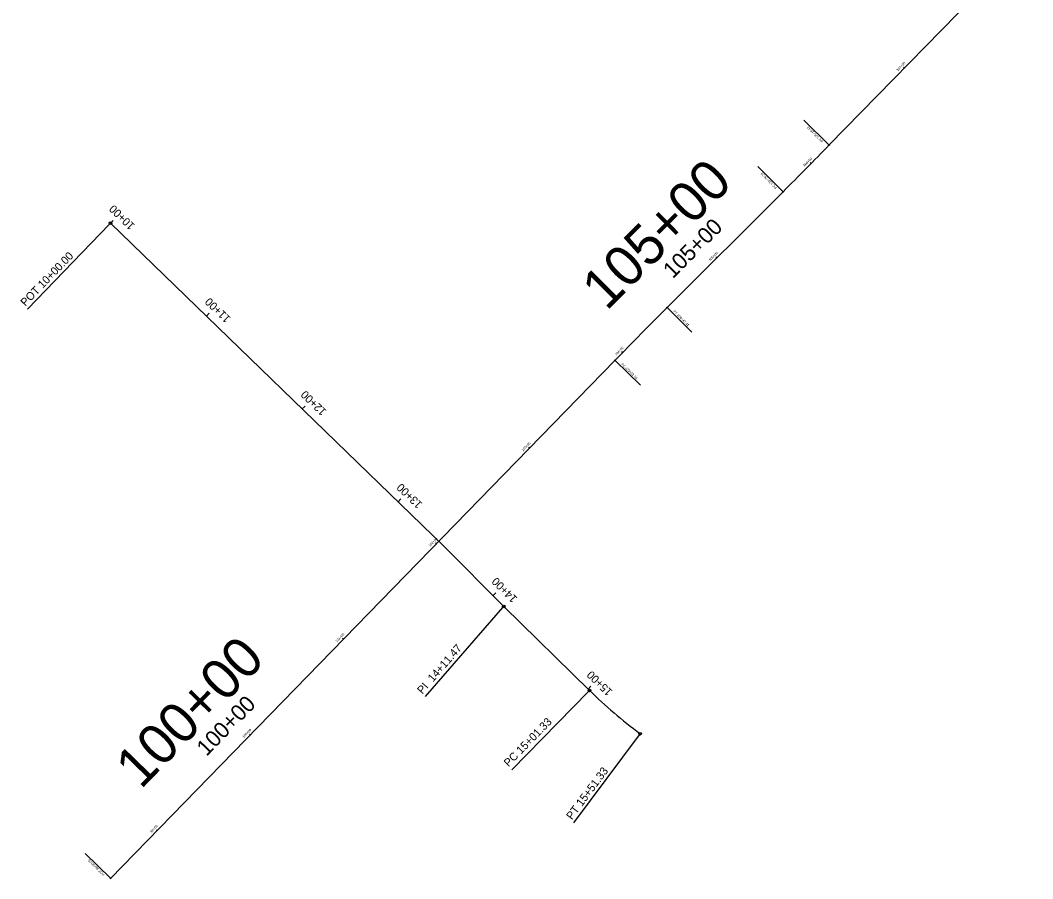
# Model space of a CAD drawing. Extents: x 2252491 to 2257126, y 13788370 to 13792743.
# Drawn here: x 2252491 to 2253250, y 13788370 to 13789013 of the extents above; entities that cross this region are included whole.
import ezdxf

# ---------------------------------------------------------------- set-up
doc = ezdxf.new("R2010")
doc.units = 0
for name, color, linetype in [('D_ALIGN_1', 7, 'Continuous'), ('D_ALIGN_ANNO_1', 7, 'Continuous'), ('D_ALIGN_ANNO_200_drn', 7, 'Continuous'), ('D_ALIGN_ANNO_DRN_300', 7, 'Continuous'), ('D_ALIGN_ANNO_S_WALNUT', 7, 'Continuous'), ('D_ALIGN_S_WALNUT', 7, 'Continuous')]:
    doc.layers.add(name, color=color, linetype=linetype)

msp = doc.modelspace()

# ---------------------------------------------------------------- linework, layer by layer
at = {"layer": 'D_ALIGN_1'}
for p, q in [((2253097.12, 13788919.23), (2254099.77, 13789945.21)), ((2252975.6, 13788797.48), (2253062.5, 13788884.24)), ((2252558.47, 13788369.82), (2252936.5, 13788757.89))]:
    msp.add_line(p, q, dxfattribs=at)
for centre, start, end in [((2250236.36, 13791714.95), 314.95375, 315.65877), ((2255801.75, 13785966.77), 134.95375, 135.75083)]:
    msp.add_arc(centre, 4000, start, end, dxfattribs=at)
at = {"layer": 'D_ALIGN_ANNO_1'}
for p, q in [((2253153.44, 13788976.86), (2253152.79, 13788977.49)), ((2253096.9, 13788919.44), (2253077.98, 13788937.94)), ((2253062.29, 13788884.45), (2253043.55, 13788903.22)), ((2253083.51, 13788905.37), (2253082.87, 13788906.01)), ((2253012.82, 13788834.64), (2253012.19, 13788835.28)), ((2252975.81, 13788797.27), (2252994.11, 13788778.95)), ((2252942.25, 13788763.79), (2252941.61, 13788764.42)), ((2252936.71, 13788757.68), (2252955.7, 13788739.19)), ((2252872.47, 13788692.16), (2252871.82, 13788692.79)), ((2252802.69, 13788620.53), (2252802.05, 13788621.16)), ((2252732.91, 13788548.9), (2252732.27, 13788549.53)), ((2252663.13, 13788477.27), (2252662.49, 13788477.9)), ((2252593.36, 13788405.64), (2252592.71, 13788406.27)), ((2252558.25, 13788370.03), (2252539.25, 13788388.54))]:
    msp.add_line(p, q, dxfattribs=at)
for centre in [(2253097.12, 13788919.23), (2253062.5, 13788884.24), (2252975.6, 13788797.48), (2252936.5, 13788757.89), (2252558.47, 13788369.82)]:
    msp.add_circle(centre, 0.3, dxfattribs=at)
at = {"layer": 'D_ALIGN_ANNO_S_WALNUT'}
for p, q in [((2252558.37, 13788860.58), (2252560.46, 13788862.74)), ((2252496.18, 13788796.34), (2252557.68, 13788859.86)), ((2252630.22, 13788791.02), (2252632.31, 13788793.18)), ((2252702.06, 13788721.47), (2252704.15, 13788723.62)), ((2252773.91, 13788651.91), (2252776, 13788654.06)), ((2252844.99, 13788581.58), (2252847.12, 13788583.69)), ((2252794.54, 13788506.17), (2252852.48, 13788572.62)), ((2252916.39, 13788511.56), (2252918.48, 13788513.71)), ((2252859.15, 13788451.08), (2252916.64, 13788509.92)), ((2252905.68, 13788411.37), (2252954.75, 13788477.4))]:
    msp.add_line(p, q, dxfattribs=at)
for centre in [(2252558.37, 13788860.58), (2252853.07, 13788573.44), (2252917.34, 13788510.63), (2252955.35, 13788478.2)]:
    msp.add_circle(centre, 1, dxfattribs=at)
at = {"layer": 'D_ALIGN_S_WALNUT'}
for p, q in [((2252558.37, 13788860.58), (2252807.9, 13788619)), ((2252807.9, 13788619), (2252853.07, 13788573.44)), ((2252853.07, 13788573.44), (2252917.34, 13788510.63))]:
    msp.add_line(p, q, dxfattribs=at)
msp.add_arc((2253176.62, 13788775.99), 371, 225.66309, 233.38489, dxfattribs=at)

# ---------------------------------------------------------------- texts
at = {"layer": 'D_ALIGN_ANNO_1'}
for s, rotation, p in [('107+00', 45.65877, (2253148.51, 13788974.39)), ('PT 106+19.42', 135.65877, (2253092.63, 13788922.36)), ('106+00', 45.38058, (2253078.57, 13788902.93)), ('PC 105+70.20', 134.95375, (2253058.05, 13788887.43)), ('105+00', 44.95375, (2253007.86, 13788832.24)), ('PT 104+47.41', 314.95375, (2252980.05, 13788794.3)), ('104+00', 45.6328, (2252937.33, 13788761.33)), ('PC 103+91.76', 315.75083, (2252940.99, 13788754.77)), ('103+00', 45.75083, (2252867.55, 13788689.69)), ('102+00', 45.75083, (2252797.77, 13788618.06)), ('101+00', 45.75083, (2252727.99, 13788546.43)), ('100+00', 45.75083, (2252658.21, 13788474.8)), ('99+00', 45.75083, (2252589.06, 13788403.8)), ('POT 98+50.00', 135.75083, (2252553.97, 13788372.95))]:
    msp.add_text(s, height=1.8, rotation=rotation, dxfattribs=at).set_placement(p)
at = {"layer": 'D_ALIGN_ANNO_200_drn'}
for s, rotation, p in [('105+00', 44.95375, (2252979.78, 13788818.61)), ('100+00', 45.75083, (2252630.32, 13788460.78))]:
    msp.add_text(s, height=12, rotation=rotation, dxfattribs=at).set_placement(p)
at = {"layer": 'D_ALIGN_ANNO_DRN_300'}
for s, rotation, p in [('105+00', 44.95375, (2252930.21, 13788794.55)), ('100+00', 45.75083, (2252581.09, 13788436.04))]:
    msp.add_text(s, height=30, rotation=rotation, dxfattribs=at).set_placement(p)
at = {"layer": 'D_ALIGN_ANNO_S_WALNUT'}
for s, rotation, p in [('10+00', 135.92669, (2252577.05, 13788859.2)), ('POT 10+00.00', 45.92669, (2252494.55, 13788797.94)), ('11+00', 135.92669, (2252648.9, 13788789.64)), ('12+00', 135.92669, (2252720.74, 13788720.08)), ('13+00', 135.92669, (2252792.59, 13788650.53)), ('14+00', 134.74782, (2252863.64, 13788579.81)), ('PI  14+11.47', 48.91397, (2252792.15, 13788507.45)), ('15+00', 135.66309, (2252935.06, 13788510.09)), ('PC 15+01.33', 45.66309, (2252856.78, 13788452.95)), ('PT 15+51.33', 53.38489, (2252904.25, 13788413.23))]:
    msp.add_text(s, height=6, rotation=rotation, dxfattribs=at).set_placement(p)

doc.saveas('drawing.dxf')
